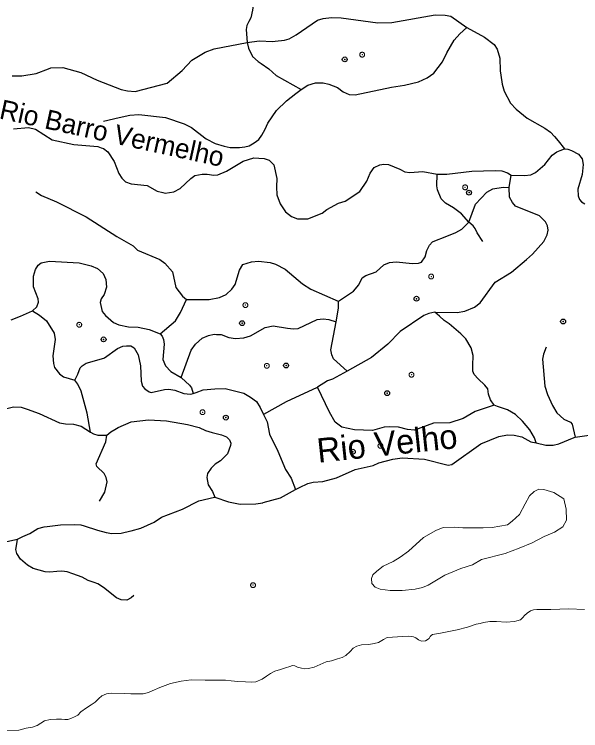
# Model space of a CAD drawing. Extents: x 267.7 to 296, y 7537.7 to 7565.8.
# Drawn here: x 269.938 to 272.267, y 7552.473 to 7555.422 of the extents above; entities that cross this region are included whole.
import ezdxf
from ezdxf.enums import TextEntityAlignment as Align

# ---------------------------------------------------------------- set-up
doc = ezdxf.new("R2010")
doc.units = 0
doc.header["$LTSCALE"] = 0.04
doc.header["$PDMODE"] = 32
doc.header["$PDSIZE"] = 0.02
doc.linetypes.add('SHORT_DASHED', pattern=[2.7, 1.5, -1.2])
doc.layers.add('21', color=7, linetype='SHORT_DASHED', lineweight=13)
doc.layers.add('7', color=7, linetype='Continuous', lineweight=25)
doc.layers.add('54', color=7, linetype='Continuous')
doc.layers.add('61', color=7, linetype='Continuous')

msp = doc.modelspace()

# ---------------------------------------------------------------- linework, layer by layer
at = {"layer": '21'}
msp.add_lwpolyline([(271.6403, 7553.0725), (271.7079, 7553.1134), (271.7742, 7553.1402), (271.8227, 7553.1555), (271.8597, 7553.1772), (271.9567, 7553.2027), (272.0141, 7553.2244), (272.0676, 7553.246), (272.1174, 7553.2728), (272.1595, 7553.2907), (272.1939, 7553.3124), (272.2092, 7553.3404), (272.208, 7553.3851), (272.1978, 7553.4272), (272.1569, 7553.454), (272.1161, 7553.4667), (272.0957, 7553.468), (272.0753, 7553.4578), (272.0562, 7553.4399), (272.0383, 7553.4068), (272.0153, 7553.3634), (271.986, 7553.3353), (271.9656, 7553.32), (271.9031, 7553.3098), (271.8661, 7553.3085), (271.7819, 7553.3085), (271.7462, 7553.3111), (271.7015, 7553.3098), (271.6709, 7553.2971), (271.6212, 7553.269), (271.5587, 7553.2116), (271.5242, 7553.1874), (271.4961, 7553.1695), (271.4553, 7553.1504), (271.4285, 7553.13), (271.412, 7553.1146), (271.4069, 7553.0993), (271.4081, 7553.0789), (271.4222, 7553.0636), (271.4426, 7553.056), (271.4834, 7553.0496), (271.5331, 7553.0496), (271.5867, 7553.056), (271.6161, 7553.0623)], close=True, dxfattribs=at)
for points in [[(272.2829, 7552.9718), (272.2187, 7552.9754), (272.1444, 7552.9718), (272.0867, 7552.9718), (272.0737, 7552.971), (272.0607, 7552.9667), (272.0477, 7552.9573), (272.0362, 7552.9472), (272.0297, 7552.9393), (272.0196, 7552.9299), (272.0051, 7552.9249), (271.995, 7552.922), (271.9604, 7552.9198), (271.9214, 7552.9227), (271.894, 7552.922), (271.8673, 7552.9191), (271.8536, 7552.9148), (271.837, 7552.9119), (271.8017, 7552.8989), (271.7598, 7552.8888), (271.6905, 7552.8751), (271.6582, 7552.8696), (271.6516, 7552.865), (271.6487, 7552.8614), (271.6444, 7552.852), (271.6285, 7552.8426), (271.6119, 7552.8412), (271.5996, 7552.8476), (271.5888, 7552.8556), (271.5794, 7552.8599), (271.5607, 7552.8628), (271.5361, 7552.8614), (271.4712, 7552.857), (271.456, 7552.8484), (271.4351, 7552.8361), (271.4178, 7552.8318), (271.3961, 7552.8274), (271.3658, 7552.826), (271.3471, 7552.8217), (271.3319, 7552.813), (271.3189, 7552.7986), (271.3016, 7552.7827), (271.2865, 7552.7748), (271.2663, 7552.769), (271.2417, 7552.7611), (271.2201, 7552.756), (271.1955, 7552.7459), (271.171, 7552.7351), (271.1479, 7552.7293), (271.1313, 7552.7279), (271.1183, 7552.73), (271.1025, 7552.7351), (271.0916, 7552.7394), (271.0815, 7552.7409), (271.0707, 7552.7372), (271.0527, 7552.7315), (271.0325, 7552.725), (271.0094, 7552.7178), (270.9913, 7552.7091), (270.9755, 7552.6976), (270.9574, 7552.6853), (270.9314, 7552.6745), (270.912, 7552.673), (270.8882, 7552.6745), (270.8564, 7552.6752), (270.8297, 7552.6781), (270.8059, 7552.681), (270.7633, 7552.6817), (270.7229, 7552.6817), (270.6652, 7552.6831), (270.6241, 7552.6766), (270.58, 7552.6673), (270.5367, 7552.6514), (270.505, 7552.6377), (270.4898, 7552.6297), (270.4682, 7552.6254), (270.4567, 7552.6254), (270.417, 7552.6254), (270.3924, 7552.6261), (270.3362, 7552.6276), (270.3167, 7552.6254), (270.2979, 7552.616), (270.2849, 7552.6052), (270.2698, 7552.5908), (270.2539, 7552.5792), (270.2344, 7552.5677), (270.2106, 7552.5511), (270.1987, 7552.5368), (270.1877, 7552.5313), (270.17, 7552.5231), (270.1577, 7552.519)], [(270.1577, 7552.519), (270.1453, 7552.519), (270.1317, 7552.5204), (270.1112, 7552.5204), (270.0852, 7552.519), (270.0619, 7552.5135), (270.0318, 7552.4944), (270.0122, 7552.4876), (269.9869, 7552.484), (269.9566, 7552.4753), (269.8967, 7552.4731)]]:
    msp.add_lwpolyline(points, dxfattribs=at)
for p in [(271.3685, 7555.2564), (271.7919, 7554.7102), (271.6523, 7554.3428), (270.888, 7554.2252), (270.2046, 7554.1444), (270.9762, 7553.9753), (271.5714, 7553.9386), (270.7117, 7553.7843), (271.4434, 7553.6459), (270.9195, 7553.0722)]:
    msp.add_point(p, dxfattribs=at)
at = {"layer": '54'}
for p in [(271.2967, 7555.2369), (271.8079, 7554.6883), (271.5917, 7554.2515), (270.8744, 7554.151), (272.1949, 7554.1577), (270.3047, 7554.084), (271.0554, 7553.9767), (271.471, 7553.8628), (270.8074, 7553.7622), (271.3302, 7553.6215)]:
    msp.add_point(p, dxfattribs=at)
at = {"layer": '7'}
msp.add_line((271.9737, 7554.7097), (271.9808, 7554.7598), dxfattribs=at)
for points in [[(270.9168, 7555.6155), (270.9171, 7555.5791), (270.9254, 7555.5321), (270.9269, 7555.5011), (270.9172, 7555.4398), (270.9108, 7555.4082), (270.9018, 7555.3925), (270.8946, 7555.3761), (270.8915, 7555.3607), (270.8947, 7555.3062)], [(270.8947, 7555.3062), (270.9451, 7555.3128), (271.0003, 7555.3113), (271.011, 7555.3123), (271.0494, 7555.3159), (271.0676, 7555.3212), (271.0975, 7555.3382), (271.1848, 7555.3986), (271.2075, 7555.4058), (271.2426, 7555.4098), (271.2818, 7555.4079), (271.4324, 7555.3875), (271.4903, 7555.3887), (271.6692, 7555.4198), (271.7101, 7555.4197), (271.7328, 7555.4143), (271.799, 7555.3683)], [(271.1171, 7555.1129), (271.1448, 7555.1308), (271.176, 7555.1409), (271.2081, 7555.1409), (271.2313, 7555.1356), (271.2676, 7555.1209), (271.29, 7555.1038), (271.3144, 7555.0928), (271.3397, 7555.091), (271.4884, 7555.1227), (271.5424, 7555.1305), (271.6003, 7555.1448), (271.6351, 7555.161), (271.6633, 7555.1799), (271.6993, 7555.2274), (271.7164, 7555.2646), (271.7467, 7555.3157), (271.7697, 7555.3427), (271.799, 7555.3683)], [(271.799, 7555.3683), (271.872, 7555.3281), (271.9116, 7555.2981), (271.9232, 7555.2793), (271.9351, 7555.2421), (271.9362, 7555.1896), (271.943, 7555.1442), (271.9444, 7555.1346), (271.953, 7555.1063), (271.9784, 7555.0562), (272.0017, 7555.0315), (272.0468, 7554.9947), (272.1193, 7554.9544), (272.1429, 7554.9371), (272.1592, 7554.9192), (272.1753, 7554.9015), (272.2003, 7554.8681)], [(269.9288, 7555.1688), (269.9687, 7555.1689), (270.028, 7555.1791), (270.0776, 7555.1985), (270.0878, 7555.2025), (270.1366, 7555.2036), (270.2114, 7555.1829), (270.2789, 7555.1511), (270.3777, 7555.113), (270.403, 7555.1074), (270.4348, 7555.1051), (270.4353, 7555.1051), (270.566, 7555.1393), (270.6274, 7555.1907), (270.6681, 7555.2342), (270.7224, 7555.2667), (270.7593, 7555.2808), (270.8947, 7555.3062)], [(270.8947, 7555.3062), (270.901, 7555.2836), (270.9175, 7555.2492), (270.9408, 7555.2282), (270.9525, 7555.22), (270.9841, 7555.1979), (271.0149, 7555.1713), (271.1171, 7555.1129)], [(270.3049, 7554.9822), (270.3692, 7554.9972), (270.4128, 7555.0074), (270.4497, 7555.0106), (270.5597, 7554.998), (270.6361, 7554.9722), (270.6659, 7554.9565), (270.7206, 7554.9145), (270.7271, 7554.9095), (270.7642, 7554.8906), (270.8012, 7554.8793), (270.8258, 7554.8742), (270.8632, 7554.874), (270.8854, 7554.8763), (270.903, 7554.8815), (270.9242, 7554.8932), (270.9428, 7554.907), (270.9552, 7554.9255), (270.9688, 7554.9503), (270.9807, 7554.975), (271.0166, 7555.0271), (271.057, 7555.0659), (271.0958, 7555.0969), (271.1171, 7555.1129)], [(269.9345, 7554.9514), (269.9953, 7554.9571), (270.0248, 7554.9498), (270.0932, 7554.9058), (270.1825, 7554.887), (270.2813, 7554.8787), (270.2953, 7554.8735), (270.3046, 7554.8701), (270.3225, 7554.8558), (270.3489, 7554.8164), (270.3672, 7554.767), (270.3797, 7554.7473), (270.3943, 7554.7328), (270.4183, 7554.7247), (270.4845, 7554.7178), (270.5247, 7554.6938), (270.5487, 7554.6887), (270.5574, 7554.6868), (270.5939, 7554.6911), (270.6202, 7554.7055), (270.6633, 7554.7472), (270.6797, 7554.7588), (270.7096, 7554.7648), (270.7304, 7554.7644), (270.7578, 7554.76), (270.774, 7554.7616), (270.8097, 7554.7767), (270.8794, 7554.8178), (270.9232, 7554.8312), (270.9438, 7554.8309), (270.9654, 7554.829), (270.9859, 7554.8219), (271.0044, 7554.8034), (271.018, 7554.7472), (271.0155, 7554.7117), (271.0174, 7554.6797), (271.0306, 7554.6422), (271.0534, 7554.6095), (271.078, 7554.5906), (271.103, 7554.5807), (271.1446, 7554.5799), (271.2036, 7554.604), (271.2227, 7554.6195), (271.2706, 7554.6454), (271.2978, 7554.6533), (271.3584, 7554.6931), (271.3872, 7554.7361), (271.4013, 7554.768), (271.418, 7554.792), (271.4405, 7554.8028), (271.4571, 7554.8057), (271.4773, 7554.8045), (271.5238, 7554.7849), (271.5433, 7554.7736), (271.5638, 7554.7716), (271.6177, 7554.7752), (271.6767, 7554.764)], [(271.9808, 7554.7598), (271.9809, 7554.7605), (272.0364, 7554.7594), (272.0621, 7554.7622), (272.0811, 7554.7716), (272.1191, 7554.8044), (272.1499, 7554.8424), (272.1687, 7554.8564), (272.1827, 7554.8619), (272.2003, 7554.8681)], [(272.2003, 7554.8681), (272.2146, 7554.868), (272.2296, 7554.8621), (272.2581, 7554.8472), (272.2727, 7554.8282), (272.2772, 7554.8043), (272.2739, 7554.7629), (272.2557, 7554.7022), (272.2564, 7554.6755), (272.2621, 7554.6598), (272.27, 7554.6504), (272.284, 7554.6418)], [(271.6767, 7554.764), (271.6778, 7554.7638), (271.7162, 7554.7638), (271.82, 7554.777), (271.9149, 7554.7798), (271.9426, 7554.7787), (271.9662, 7554.7705), (271.9808, 7554.7598)], [(271.8077, 7554.5663), (271.777, 7554.6012), (271.7443, 7554.626), (271.711, 7554.6445), (271.6936, 7554.6628), (271.6779, 7554.6995), (271.6754, 7554.7157), (271.6767, 7554.764)], [(270.0256, 7554.6911), (270.0493, 7554.6768), (270.1107, 7554.6499), (270.2337, 7554.5887), (270.3597, 7554.5071), (270.4264, 7554.4688), (270.4439, 7554.4517), (270.5358, 7554.4125), (270.5571, 7554.3986), (270.5888, 7554.3625), (270.6023, 7554.298), (270.6299, 7554.2624), (270.6463, 7554.2478)], [(271.6675, 7554.1968), (271.7596, 7554.1952), (271.7901, 7554.2001), (271.8307, 7554.2164), (271.8542, 7554.2351), (271.9151, 7554.3197), (271.9826, 7554.361), (272.0444, 7554.4131), (272.0694, 7554.4349), (272.1152, 7554.4876), (272.1287, 7554.5143), (272.1329, 7554.5344), (272.1314, 7554.552), (272.1227, 7554.5675), (272.0977, 7554.593), (271.9997, 7554.6329), (271.9867, 7554.6474), (271.9749, 7554.6703), (271.9737, 7554.7097)], [(271.8077, 7554.5663), (271.8351, 7554.6404), (271.8816, 7554.6909), (271.9058, 7554.7036), (271.9481, 7554.7102), (271.9737, 7554.7097)], [(271.2704, 7554.2411), (271.3321, 7554.2822), (271.3553, 7554.3084), (271.368, 7554.338), (271.3831, 7554.3477), (271.4259, 7554.3629), (271.4578, 7554.3912), (271.4811, 7554.4007), (271.5083, 7554.404), (271.5751, 7554.3969), (271.6006, 7554.3979), (271.6124, 7554.4027), (271.6275, 7554.4246), (271.6346, 7554.4503), (271.6458, 7554.4718), (271.6572, 7554.4852), (271.6735, 7554.493), (271.7024, 7554.5037), (271.753, 7554.5238), (271.7782, 7554.538), (271.8077, 7554.5663)], [(271.8641, 7554.4877), (271.8411, 7554.5232), (271.8338, 7554.5406), (271.8245, 7554.5519), (271.8077, 7554.5663)], [(270.0118, 7554.2016), (270.0295, 7554.2179), (270.0363, 7554.2371), (270.0361, 7554.251), (270.0158, 7554.3003), (270.0167, 7554.3449), (270.0253, 7554.3713), (270.0355, 7554.3898), (270.0482, 7554.3999), (270.0821, 7554.4064), (270.2049, 7554.3987), (270.2537, 7554.3865), (270.2791, 7554.3759), (270.3025, 7554.3555), (270.3143, 7554.3303), (270.3165, 7554.2986), (270.3075, 7554.2688), (270.2945, 7554.2506), (270.2907, 7554.2354), (270.2988, 7554.1987), (270.3132, 7554.182), (270.346, 7554.1534), (270.3672, 7554.144), (270.4077, 7554.1364), (270.4464, 7554.1339), (270.4917, 7554.1243), (270.5376, 7554.1064)], [(270.6463, 7554.2478), (270.7088, 7554.2481), (270.7388, 7554.2482), (270.7809, 7554.257), (270.8096, 7554.2685), (270.8329, 7554.2905), (270.8459, 7554.31), (270.8636, 7554.3686), (270.8781, 7554.3919), (270.9129, 7554.4041), (270.9418, 7554.4056), (270.9894, 7554.4004), (271.0125, 7554.3937), (271.0516, 7554.373), (271.1225, 7554.3129), (271.1571, 7554.2907), (271.2702, 7554.241), (271.2704, 7554.2411)], [(270.5376, 7554.1064), (270.6002, 7554.1603), (270.6214, 7554.1955), (270.6463, 7554.2478)], [(271.2612, 7554.1565), (271.2717, 7554.2126), (271.2704, 7554.2411)], [(269.9246, 7554.165), (269.9626, 7554.1803), (270.0118, 7554.2016)], [(270.0118, 7554.2016), (270.0415, 7554.184), (270.0703, 7554.1607), (270.101, 7554.1095), (270.1061, 7554.0834), (270.0965, 7554.0161), (270.0983, 7553.9844), (270.1022, 7553.969), (270.1239, 7553.9417), (270.1399, 7553.9299), (270.1867, 7553.9156), (270.1868, 7553.9159)], [(271.6675, 7554.1968), (271.6429, 7554.1906), (271.6214, 7554.1829), (271.5243, 7554.1165), (271.4733, 7554.0648), (271.4062, 7554.0095), (271.306, 7553.9536)], [(271.9107, 7553.8129), (271.8957, 7553.8355), (271.8882, 7553.8591), (271.8851, 7553.8802), (271.8728, 7553.896), (271.8461, 7553.9217), (271.8297, 7553.9402), (271.8235, 7553.9535), (271.8235, 7553.9771), (271.8248, 7554.0181), (271.8173, 7554.049), (271.7948, 7554.0869), (271.7741, 7554.1071), (271.7257, 7554.1479), (271.7052, 7554.1615), (271.687, 7554.1793), (271.6675, 7554.1968)], [(270.6232, 7553.9277), (270.6647, 7554.0396), (270.6823, 7554.0648), (270.7099, 7554.089), (270.7359, 7554.1002), (270.7591, 7554.1054), (270.7697, 7554.1048), (270.789, 7554.1038), (270.8193, 7554.0921), (270.8468, 7554.088), (270.881, 7554.0904), (270.9095, 7554.0982), (270.9689, 7554.1329), (271.0024, 7554.1402), (271.0609, 7554.1301), (271.0855, 7554.127), (271.105, 7554.129), (271.1836, 7554.1657), (271.2074, 7554.169), (271.2312, 7554.1658), (271.2612, 7554.1565)], [(271.306, 7553.9536), (271.25, 7554.0039), (271.2432, 7554.0209), (271.2396, 7554.0415), (271.2612, 7554.1565)], [(270.5376, 7554.1064), (270.5453, 7554.0974), (270.5506, 7554.0835), (270.5534, 7554.0646), (270.5487, 7554.002), (270.5594, 7553.9749), (270.5807, 7553.9524), (270.6232, 7553.9277)], [(270.1868, 7553.9159), (270.1987, 7553.9412), (270.209, 7553.9669), (270.2161, 7553.9751), (270.2336, 7553.9864), (270.3053, 7554.007), (270.3091, 7554.0081), (270.3623, 7554.0468), (270.3841, 7554.056), (270.3988, 7554.0572), (270.4173, 7554.0572), (270.4307, 7554.049), (270.4466, 7554.021), (270.4564, 7553.9754), (270.4596, 7553.9128), (270.4652, 7553.8921), (270.4749, 7553.88), (270.492, 7553.8681), (270.501, 7553.8656), (270.5558, 7553.8781), (270.5731, 7553.8788), (270.5972, 7553.8749), (270.6347, 7553.8618), (270.6623, 7553.8586), (270.6734, 7553.8611)], [(272.1248, 7554.0517), (272.1139, 7554.0226), (272.1105, 7554.0026), (272.1204, 7553.8918), (272.1306, 7553.8566), (272.1507, 7553.8124), (272.1694, 7553.7824), (272.1982, 7553.7558), (272.2249, 7553.7431), (272.2319, 7553.7349), (272.2442, 7553.6812)], [(272.2442, 7553.6812), (272.3116, 7553.6913), (272.3421, 7553.6854), (272.3667, 7553.6747), (272.3922, 7553.6714), (272.4305, 7553.6788), (272.4688, 7553.6941), (272.5525, 7553.7457), (272.6109, 7553.7742), (272.6704, 7553.7954), (272.7019, 7553.8134), (272.761, 7553.8716), (272.808, 7553.9564), (272.8328, 7554.0311), (272.8481, 7554.0466), (272.8712, 7554.0517)], [(271.306, 7553.9536), (271.2469, 7553.9206), (271.226, 7553.9129), (271.1843, 7553.8868)], [(270.2511, 7553.7026), (270.2365, 7553.7807), (270.2124, 7553.8703), (270.1991, 7553.8991), (270.1868, 7553.9159)], [(270.6232, 7553.9277), (270.6252, 7553.9265), (270.6578, 7553.8962), (270.6658, 7553.8841), (270.6734, 7553.8611)], [(271.1843, 7553.8868), (271.1838, 7553.8865), (271.0553, 7553.8273), (270.9625, 7553.7752)], [(271.9107, 7553.8129), (271.8335, 7553.7866), (271.7836, 7553.759), (271.7286, 7553.7399), (271.6624, 7553.7389), (271.5831, 7553.711), (271.5547, 7553.7137), (271.5176, 7553.7222), (271.4796, 7553.7246), (271.459, 7553.7224), (271.4103, 7553.7088), (271.3363, 7553.7115), (271.2847, 7553.7229), (271.2577, 7553.743), (271.2334, 7553.7844), (271.1843, 7553.8868)], [(270.6734, 7553.8611), (270.6852, 7553.8652), (270.7139, 7553.8765), (270.7619, 7553.8811), (270.8042, 7553.8826), (270.8815, 7553.8631), (270.8881, 7553.8592), (270.909, 7553.8468), (270.9331, 7553.828), (270.9483, 7553.8039), (270.9625, 7553.7752)], [(269.8907, 7553.7956), (269.9336, 7553.8068), (269.9663, 7553.8056), (269.9908, 7553.7966), (270.0404, 7553.7784), (270.1232, 7553.7411), (270.1481, 7553.7364), (270.1804, 7553.7353), (270.213, 7553.7272), (270.2511, 7553.7026)], [(272.0835, 7553.6578), (272.0779, 7553.6793), (272.0577, 7553.7123), (272.0279, 7553.748), (271.9986, 7553.7746), (271.9668, 7553.7941), (271.9251, 7553.8078), (271.9107, 7553.8129)], [(270.9625, 7553.7752), (270.9773, 7553.7453), (270.9878, 7553.6934), (271.0219, 7553.6244), (271.0535, 7553.5478), (271.0769, 7553.5121), (271.0935, 7553.4659)], [(270.3183, 7553.6898), (270.334, 7553.7031), (270.3514, 7553.7133), (270.3643, 7553.7209), (270.4182, 7553.745), (270.489, 7553.7526), (270.5641, 7553.7484), (270.6498, 7553.734), (270.6978, 7553.7213), (270.7233, 7553.7094), (270.7519, 7553.701), (270.7899, 7553.6907), (270.8107, 7553.6825), (270.8221, 7553.6709), (270.8275, 7553.6562), (270.827, 7553.6468), (270.8148, 7553.6126), (270.7855, 7553.5835), (270.7643, 7553.5709), (270.7467, 7553.5534), (270.7327, 7553.5325), (270.7293, 7553.5148), (270.7352, 7553.4851), (270.753, 7553.4578), (270.7619, 7553.4348)], [(270.2511, 7553.7026), (270.2628, 7553.695), (270.2812, 7553.69), (270.3182, 7553.6897), (270.3183, 7553.6898)], [(270.2882, 7553.4175), (270.3105, 7553.4553), (270.3201, 7553.4979), (270.316, 7553.515), (270.307, 7553.5314), (270.2772, 7553.5606), (270.2748, 7553.5712), (270.3138, 7553.6623), (270.3183, 7553.6898)], [(271.0935, 7553.4659), (271.1101, 7553.4742), (271.145, 7553.4906), (271.1669, 7553.4959), (271.2059, 7553.4991), (271.2626, 7553.514), (271.3393, 7553.5487), (271.413, 7553.5653), (271.437, 7553.5758), (271.4948, 7553.5912), (271.5332, 7553.5965), (271.6245, 7553.5908), (271.7216, 7553.5668), (271.7374, 7553.5686), (271.8561, 7553.6543), (271.9302, 7553.6845), (271.9663, 7553.691), (271.9931, 7553.6895), (272.0256, 7553.6825), (272.0617, 7553.6625), (272.0835, 7553.6578)], [(272.0835, 7553.6578), (272.1245, 7553.6489), (272.1275, 7553.6482), (272.1541, 7553.6484), (272.177, 7553.6544), (272.241, 7553.6807), (272.2442, 7553.6812)], [(270.7619, 7553.4348), (270.8183, 7553.4154), (270.8667, 7553.4054), (270.931, 7553.4068), (270.9599, 7553.4116), (270.9613, 7553.412), (271.033, 7553.4318), (271.0935, 7553.4659)], [(269.95, 7553.2618), (269.9508, 7553.262), (269.9729, 7553.272), (270.0009, 7553.2849), (270.034, 7553.3055), (270.0597, 7553.3117), (270.0732, 7553.3133), (270.1276, 7553.32), (270.1833, 7553.3223), (270.211, 7553.3202), (270.2254, 7553.3161), (270.2798, 7553.2987), (270.3147, 7553.2891), (270.3381, 7553.2855), (270.3773, 7553.2863), (270.4163, 7553.2956), (270.4184, 7553.2962), (270.4579, 7553.307), (270.5121, 7553.3316), (270.5428, 7553.3523), (270.6289, 7553.3852), (270.697, 7553.4193), (270.7615, 7553.4349), (270.7619, 7553.4348)], [(269.4299, 7552.9302), (269.4597, 7552.9343), (269.5098, 7552.9394), (269.5396, 7552.9388), (269.5751, 7552.945), (269.6106, 7552.9528), (269.615, 7552.9546), (269.6425, 7552.9659), (269.6609, 7552.9782), (269.6786, 7552.999), (269.6991, 7553.036), (269.7104, 7553.0698), (269.7169, 7553.1089), (269.7317, 7553.1445), (269.7534, 7553.1745), (269.7817, 7553.1993), (269.8307, 7553.2303), (269.8558, 7553.2411), (269.95, 7553.2618)], [(270.4288, 7553.0299), (270.4183, 7553.0195), (270.4003, 7553.0107), (270.3775, 7553.0116), (270.3578, 7553.0205), (270.3042, 7553.0621), (270.2808, 7553.078), (270.2655, 7553.0836), (270.2408, 7553.0913), (270.2172, 7553.1047), (270.1779, 7553.1192), (270.1546, 7553.1272), (270.1325, 7553.1294), (270.1119, 7553.1281), (270.0837, 7553.1262), (270.0647, 7553.1272), (270.0155, 7553.1407), (269.9924, 7553.1542), (269.9626, 7553.1786), (269.9472, 7553.2022), (269.9441, 7553.2196), (269.9472, 7553.2422), (269.95, 7553.2618)]]:
    msp.add_lwpolyline(points, dxfattribs=at)

# ---------------------------------------------------------------- texts
at = {"layer": '61'}
for s, height, rotation, p in [('Rio Barro Vermelho', 0.08, 347.672, (270.3308, 7554.8942)), ('Rio Velho', 0.1, 6.05, (271.4761, 7553.6065))]:
    msp.add_text(s, height=height, rotation=rotation, dxfattribs=at).set_placement(p, align=Align.CENTER)

doc.saveas('drawing.dxf')
